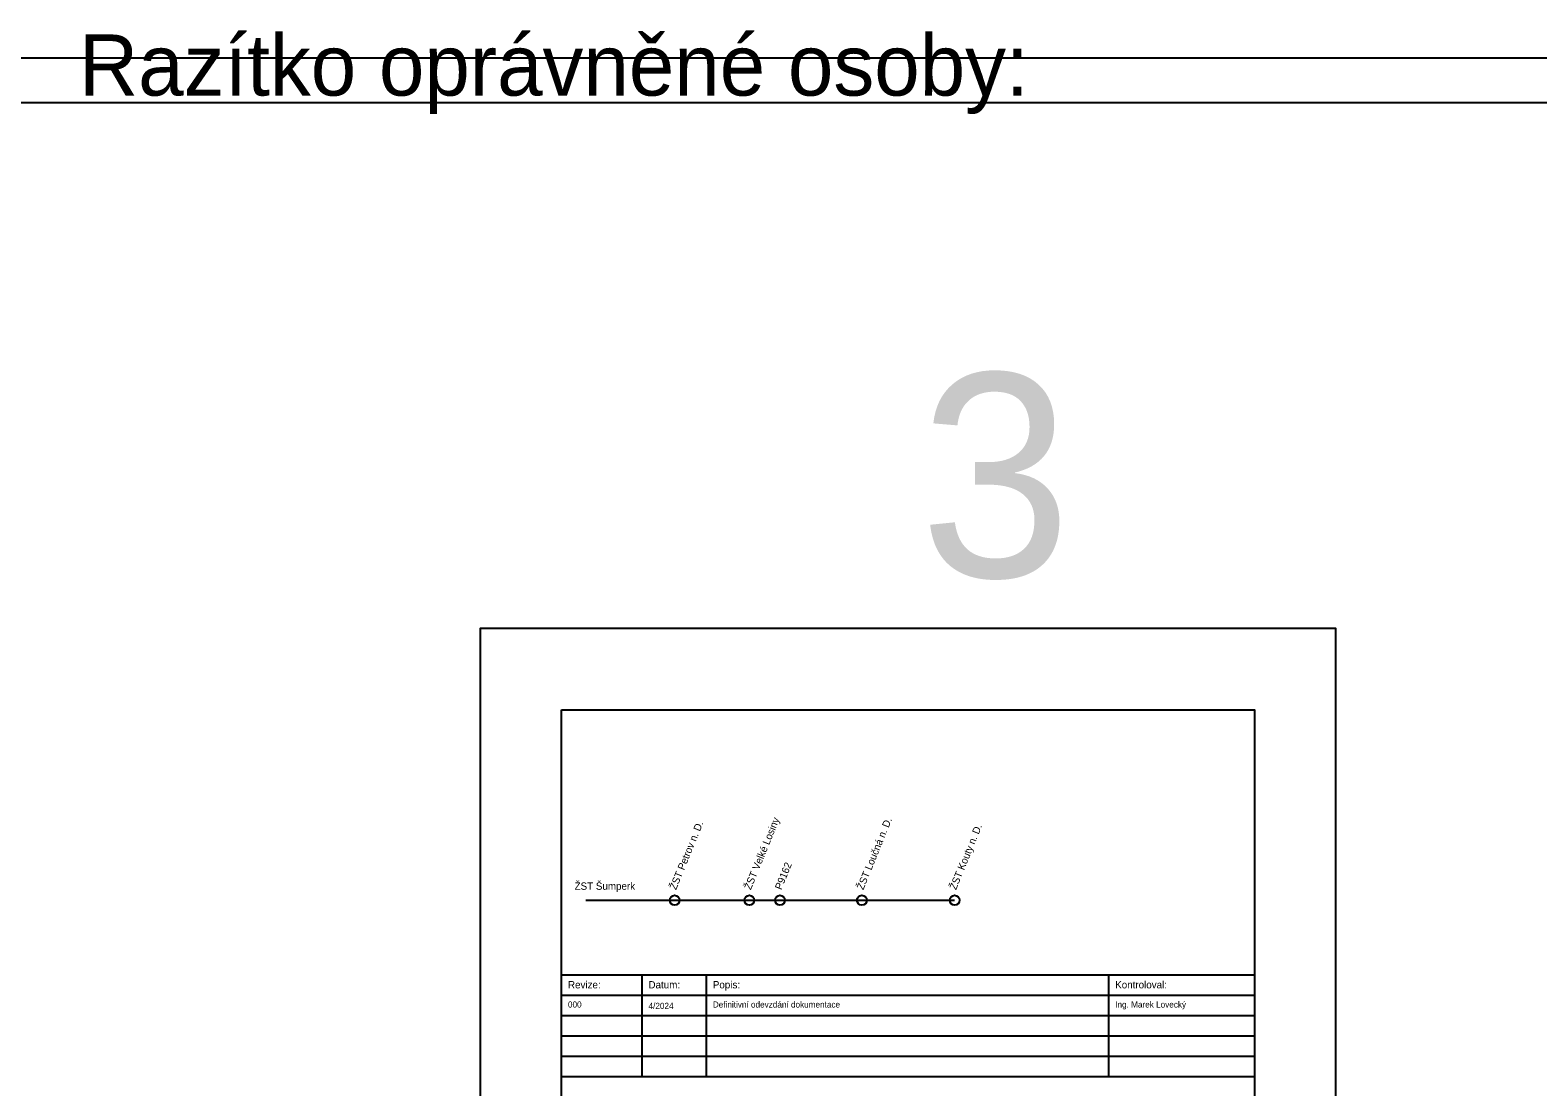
# Model space of a CAD drawing. Extents: x 1391 to 5528, y -6194 to 565.
# Drawn here: x 3815.1 to 4185.1, y -1452.2 to -1192.9 of the extents above; entities that cross this region are included whole.
import ezdxf

# ---------------------------------------------------------------- set-up
doc = ezdxf.new("R2010")
doc.units = 0
for name, color, linetype in [('Default', 7, 'Continuous'), ('Vrstva 1', 7, 'Continuous'), ('Vrstva 11', 7, 'Continuous'), ('Vrstva 2', 7, 'Continuous'), ('Vrstva 3', 7, 'Continuous'), ('Vrstva 4', 7, 'Continuous'), ('Vrstva 6', 7, 'Continuous'), ('Vrstva 7', 7, 'Continuous')]:
    doc.layers.add(name, color=color, linetype=linetype)

# ---------------------------------------------------------------- blocks, each defined once
blk = doc.blocks.new('_U2')
at = {"layer": 'Vrstva 3'}
blk.add_text('Razítko oprávněné osoby:', height=0.15, dxfattribs=at).set_placement((-2.5675, 1.92495))
blk = doc.blocks.new('_U3')
at = {"layer": 'Vrstva 2'}
blk.add_lwpolyline([(-5.33255, 2.00005), (5.33245, 2.00005), (5.33245, -1.99995), (-5.33255, -1.99995)], close=True, dxfattribs=at)

msp = doc.modelspace()

# ---------------------------------------------------------------- linework, layer by layer
at = {"layer": 'Default'}
msp.add_lwpolyline([(3925.56, -1636.75), (4135.56, -1636.75), (4135.56, -1339.75), (3925.56, -1339.75)], close=True, dxfattribs=at)
at = {"layer": 'Vrstva 1'}
msp.add_lwpolyline([(3945.56, -1359.75), (4115.56, -1359.75), (4115.56, -1619.75), (3945.56, -1619.75)], close=True, dxfattribs=at)
at = {"layer": 'Vrstva 11'}
msp.add_line((1390.73, -1210.73), (5438.99, -1210.73), dxfattribs=at)
msp.add_lwpolyline([(3951.49, -1406.45), (4041.99, -1406.45)], dxfattribs=at)
for centre in [(3973.28, -1406.45), (3991.63, -1406.45), (3991.63, -1406.45), (3999.14, -1406.45), (4019.24, -1406.45), (4019.24, -1406.45), (4041.99, -1406.45), (4041.99, -1406.45)]:
    msp.add_circle(centre, 1.2, dxfattribs=at)
at = {"layer": 'Vrstva 4'}
for p, q in [((3965.31, -1449.75), (3965.31, -1424.75)), ((3981.11, -1449.75), (3981.11, -1424.75)), ((4079.86, -1449.75), (4079.86, -1424.75)), ((3945.56, -1429.75), (4115.56, -1429.75)), ((3945.56, -1434.75), (4115.56, -1434.75)), ((3945.56, -1439.75), (4115.56, -1439.75)), ((3945.56, -1444.75), (4115.56, -1444.75))]:
    msp.add_line(p, q, dxfattribs=at)
msp.add_lwpolyline([(3945.56, -1424.75), (4115.56, -1424.75), (4115.56, -1449.75), (3945.56, -1449.75)], close=True, dxfattribs=at)

# ---------------------------------------------------------------- block references
at = {"layer": 'Vrstva 2', "xscale": 100, "yscale": 100}
msp.add_blockref('_U3', (3998.89, -1399.75), dxfattribs=at)
at = {"layer": 'Vrstva 3', "xscale": 100, "yscale": 100}
msp.add_blockref('_U2', (4083.89, -1401.5), dxfattribs=at)

# ---------------------------------------------------------------- texts
at = {"layer": 'Vrstva 4'}
for s, height, p in [('Revize:', 1.8, (3947.11, -1428.09)), ('Datum:', 1.8, (3966.86, -1428.09)), ('Popis:', 1.8, (3982.66, -1428.09)), ('Kontroloval:', 1.8, (4081.41, -1428.09)), ('000', 1.5, (3947.11, -1432.79)), ('4/2024', 1.5, (3966.89, -1433.12)), ('Definitivní odevzdání dokumentace', 1.5, (3982.66, -1432.79)), ('Ing. Marek Lovecký', 1.5, (4081.41, -1432.79))]:
    msp.add_text(s, height=height, dxfattribs=at).set_placement(p)
at = {"layer": 'Vrstva 6'}
msp.add_text('3', height=50, dxfattribs=at).set_placement((4033.45, -1327.16))
at = {"layer": 'Vrstva 7'}
for s, p in [('ŽST Velké Losiny', (3991.97, -1404.05)), ('ŽST Loučná n. D.', (4019.58, -1404.05)), ('ŽST Petrov n. D.', (3973.63, -1404.05)), ('ŽST Kouty n. D.', (4042.34, -1404.05)), ('P9162', (3999.48, -1404.05))]:
    msp.add_text(s, height=1.8, rotation=67.8731, dxfattribs=at).set_placement(p)
msp.add_text('ŽST Šumperk', height=1.8, dxfattribs=at).set_placement((3948.74, -1403.89))

doc.saveas('drawing.dxf')
